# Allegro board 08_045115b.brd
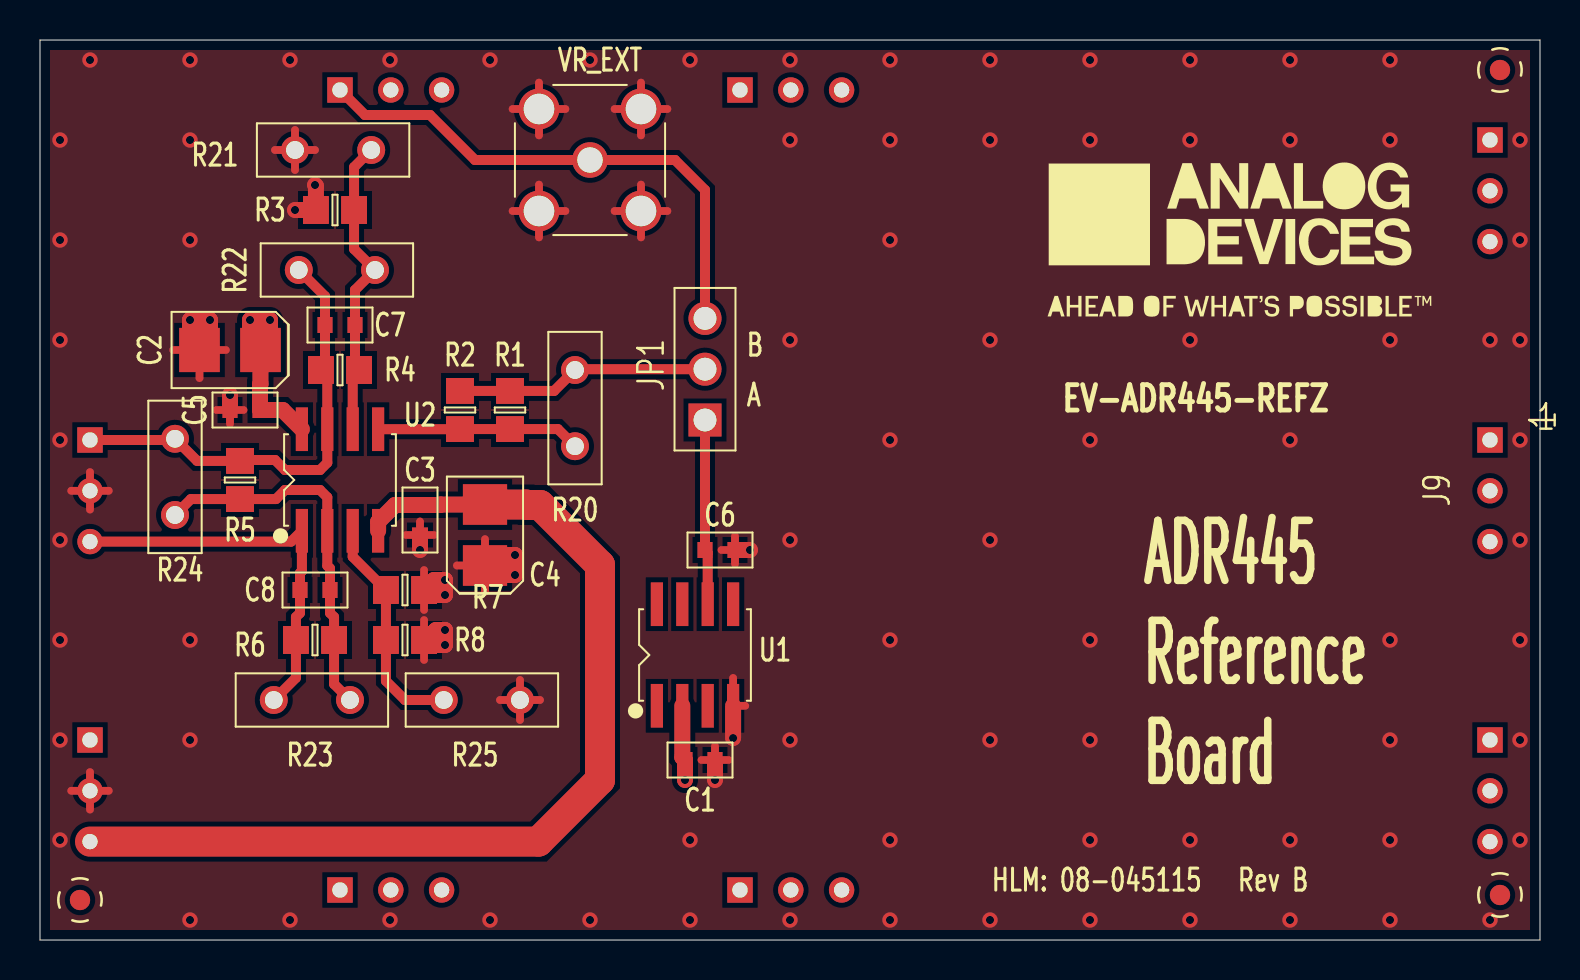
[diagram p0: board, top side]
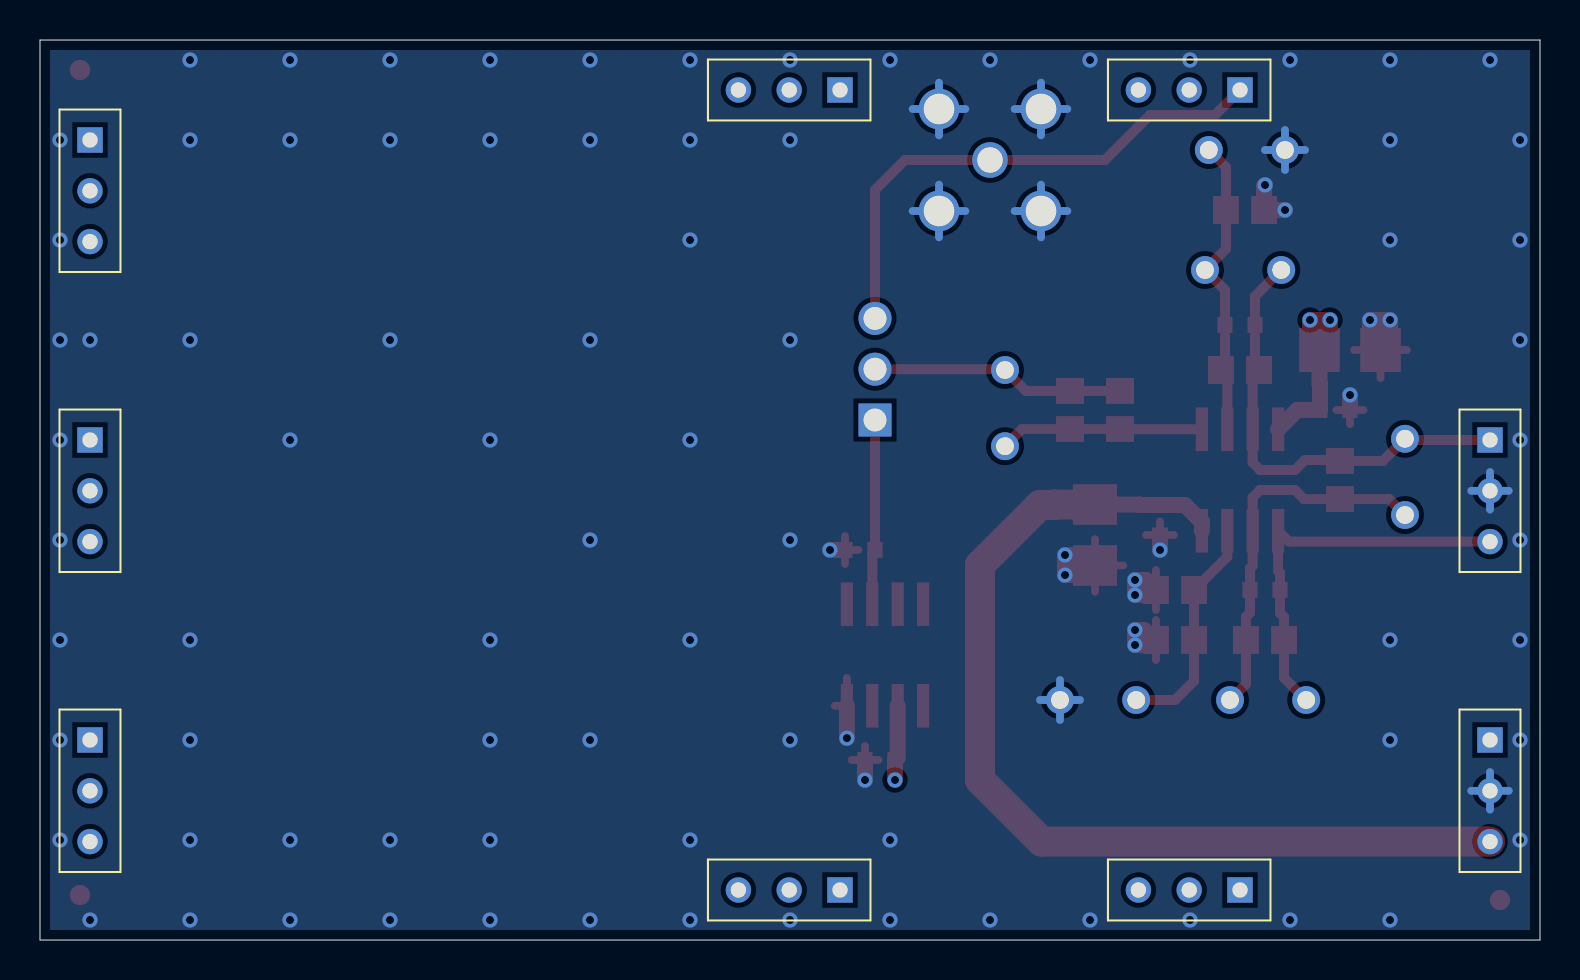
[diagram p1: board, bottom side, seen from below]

Outline 75 x 45 mm; copper layers: TOP, LAYER2, LAYER3, BOTTOM. Coordinates in mm from the lower left corner of the outline.
Outline path: 0,45 0,0 75,0 75,45 0,45

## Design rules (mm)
constraint set DEFAULT: min track width 0.19

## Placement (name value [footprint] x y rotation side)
C1  0.1UF  [C0603]  33 9 180 top
C2  10uF  [C3528]  9.5 29.5 180 top
C3  0.1UF  [C0603]  19 21 270 top
C4  10uF  [C3528]  22.25 20.25 90 top
C5  0.1UF  [C0603]  10.25 26.5 0 top
C6  0.1UF  [C0603]  34 19.5 180 top
C7  0.1UF  [C0603]  15 30.75 180 top
C8  0.1UF  [C0603]  13.75 17.5 180 top
J1  350-10-103-00-006000  [CNTHMHDR1X3L300W100H284]  2.5 10 270 bottom
J2  350-10-103-00-006000  [CNTHMHDR1X3L300W100H284]  35 42.5 0 bottom
J3  350-10-103-00-006000  [CNTHMHDR1X3L300W100H284]  15 42.5 0 bottom
J4  310-13-103-41-001000  [CNTHFHDR1X3L300W100H165]  2.5 25 270 bottom
J5  310-13-103-41-001000  [CNTHFHDR1X3L300W100H165]  72.5 40 270 bottom
J6  310-13-103-41-001000  [CNTHFHDR1X3L300W100H165]  15 2.5 0 bottom
J7  350-10-103-00-006000  [CNTHMHDR1X3L300W100H284]  35 2.5 0 bottom
J8  350-10-103-00-006000  [CNTHMHDR1X3L300W100H284]  72.5 10 270 bottom
J9  350-10-103-00-006000  [CNTHMHDR1X3L300W100H284]  72.5 25 270 bottom
JP1  M20-9990345  [CNHDR1X3H340]  33.25 26 90 top
NOREF  -  [unnamed]  73 2.25 0 top
NOREF#2  -  [#2]  0 45 0 top
NOREF#3  -  [unnamed]  73 43.5 0 top
NOREF#4  -  [unnamed]  2 2 0 top
NOREF#5  -  [#2]  -105 -95 0 top
NOREF#6  -  [#2]  36.75 -16.25 0 top
NOREF#7  -  [#2]  -100 -95 0 top
NOREF#8  -  [#2]  60 35 0 top
NOREF#9  -  [#2]  0 0 90 top
R1  10K  [R0805]  23.5 26.5 270 top
R2  10K  [R0805]  21 26.5 270 top
R3  10K  [R0805]  14.75 36.5 0 top
R4  10K  [R0805]  15 28.5 180 top
R5  10K  [R0805]  10 23 90 top
R6  10K  [R0805]  13.75 15 180 top
R7  10K  [R0805]  18.25 17.5 180 top
R8  10K  [R0805]  18.25 15 180 top
R20  10K  [RRADTH150L300H336W105LD25]  26.75 28.5 270 top
R21  10K  [RRADTH150L300H336W105LD25]  12.75 39.5 0 top
R22  10K  [RRADTH150L300H336W105LD25]  16.75 33.5 180 top
R23  10K  [RRADTH150L300H336W105LD25]  15.5 12 180 top
R24  10K  [RRADTH150L300H336W105LD25]  6.75 21.25 90 top
R25  10K  [RRADTH150L300H336W105LD25]  24 12 180 top
U1  ADR445BRZ  [SO8]  32.75 14.25 0 top
U2  ADA4077-2BRZ  [SO8]  15 23 0 top
VR_EXT  1-1337482-0  [CNBNCSQ276H299]  27.5 39 0 top

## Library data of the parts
C1 C3 C5-C8 = CAP: User Part Number: UPN; Tolerance: 10; alternate symbols: (); part number: CAP_SM-0.1UF,25V,10,E007204,C0603; tolerance: 10
C2 C4 = CAPP: User Part Number: UPN; Tolerance: N/A; alternate symbols: (); part number: CAPP_SM-10UF,N/A,N/A,E000695,C3528; tolerance: N/A
J1-J3 J7-J9 = CN3P: User Part Number: UPN; Tolerance: N/A; alternate symbols: (); part number: CN3P_TH-350-10-103-00-006000,E027762,CNTHMHDR1X3L300W100H284; tolerance: N/A
J4-J6 = CN3P: User Part Number: UPN; Tolerance: N/A; alternate symbols: (); part number: CN3P_TH-310-13-103-41-001000,E027752,CNTHFHDR1X3L300W100H165; tolerance: N/A
JP1 = CN3P_JMPRSHRT: Tolerance: N/A; User Part Number: UPN; alternate symbols: (); part number: CN3P_JMPRSHRT_TH-M20-9990345,E029424,CNHDR1X3H340; tolerance: N/A
R1-R8 = RES: User Part Number: UPN; Tolerance: 0.1; alternate symbols: (R0805L); part number: RES_SM-10K,E003806,1/8W,0.1,R0805; tolerance: 0.1
R20-R25 = RES: Tolerance: 0.005; User Part Number: UPN; alternate symbols: (); part number: RES_TH-10K,E018578,6/10W,0.005,RRADTH150L300H336W105LD25; tolerance: 0.005
U1 = ADR441: User Part Number: UPN; Tolerance: N/A; alternate symbols: (); part number: ADR441_SM-ADR445BRZ,E012504,SO8; tolerance: N/A
U2 = ADA4077_2: User Part Number: UPN; Tolerance: N/A; alternate symbols: (); part number: ADA4077_2_SM-ADA4077-2BRZ,E018506,SO8; tolerance: N/A
VR_EXT = CNBNC5P: Tolerance: N/A; User Part Number: UPN; alternate symbols: (); part number: CNBNC5P_TH-1-1337482-0,E013941,CNBNCSQ276H299; tolerance: N/A

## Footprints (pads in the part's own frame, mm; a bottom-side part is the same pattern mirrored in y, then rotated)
C0603
  rect 0.75x0.8 smd: 1(-0.75,0) 2(0.75,0)
C3528
  rect 2.032x2.21 smd: N(1.524,0) P(-1.524,0)
CNBNCSQ276H299
  round 1.778 hole 1.27: 1(0,0)
  round 2.032 hole 1.524: 2(-2.55,2.55) 3(2.55,2.55) 4(2.55,-2.55) 5(-2.55,-2.55)
CNHDR1X3H340
  rect 1.651x1.651 hole 1.143: 1(0,0)
  round 1.651 hole 1.143: 2(2.54,0) 3(5.08,0)
CNTHFHDR1X3L300W100H165
  rect 1.27x1.27 hole 0.762: 1(0,0)
  round 1.27 hole 0.762: 2(2.54,0) 3(5.08,0)
CNTHMHDR1X3L300W100H284
  rect 1.27x1.27 hole 0.762: 1(0,0)
  round 1.27 hole 0.762: 2(2.54,0) 3(5.08,0)
R0805
  rect 1.295x1.397 smd: 1(-0.953,0) 2(0.953,0)
RRADTH150L300H336W105LD25
  round 1.397 hole 0.889: 1(0,0) 2(3.81,0)
SO8
  rect 0.61x2.184 smd: 1(-1.905,-2.54) 2(-0.635,-2.54) 3(0.635,-2.54) 4(1.905,-2.54) 5(1.905,2.54) 6(0.635,2.54) 7(-0.635,2.54) 8(-1.905,2.54)
unnamed
  round 1.016 smd: (0,0)

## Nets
AGND: C1.1(N1) C2.N(N2) C3.2(N2) C4.P(N1) C5.1(N1) C6.1(N1) J1.2(N2) J4.2(N2) R3.1(N1) R7.1(N1) R8.1(N1) R21.1(N1) R25.1(N1) U1.4(GND) VR_EXT.2(SH1) VR_EXT.3(SH2) VR_EXT.4(SH3) VR_EXT.5(SH4)
VDD: C1.2(N2) C2.P(N1) C5.2(N2) J1.1(N1) U1.2(VIN) U2.8(V+)
VSS: C3.1(N1) C4.N(N2) J1.3(N3) U2.4(V-)
UNNAMED_2_ADA40772_I74_: C7.1(N1) R3.2(N2) R4.1(N1) R21.2(N2) R22.1(N1) U2.6(-IN)
UNNAMED_2_ADA40772_I74__1: R1.2(N2) R2.2(N2) R20.2(N2) U2.5(+IN)
UNNAMED_2_ADA40772_I75_: C8.1(N1) R5.1(N1) R6.1(N1) R23.1(N1) R24.1(N1) U2.2(-IN)
UNNAMED_2_ADA40772_I75__1: R7.2(N2) R8.2(N2) R25.2(N2) U2.3(+IN)
UNNAMED_2_ADR441_I1_VOUT: C6.2(N2) JP1.1(S1) U1.6(VOUT)
UNNAMED_2_CN3P_I64_N1: J3.1(N1) JP1.3(S3) VR_EXT.1(CNTR)
UNNAMED_2_CN3PJMPRSHRT_I77_S2: JP1.2(S2) R1.1(N1) R2.1(N1) R20.1(N1)
VREFN: C8.2(N2) J4.3(N3) R6.2(N2) R23.2(N2) U2.1(OUT)
VREFP: C7.2(N2) J4.1(N1) R4.2(N2) R5.2(N2) R22.2(N2) R24.2(N2) U2.7(OUT)

Pads without a net: J2 1 2 3; J3 2 3; J5 1 2 3; J6 1 2 3; J7 1 2 3; J8 1 2 3; J9 1 2 3; U1 1 3 5 7 8

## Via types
v1: diameter 0.762, hole 0.406, TOP to BOTTOM, 97 vias

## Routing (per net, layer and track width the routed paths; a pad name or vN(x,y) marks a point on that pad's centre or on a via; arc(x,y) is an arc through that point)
AGND: length 156.1
  TOP w0.39: C1.1 33.75,9.7 ; C1.1 33.07,9 ; C1.1 34.43,9 ; 19.2,14 R8.1 19.2,16 ; C4.P 23.66,18.73 ; C4.P 22.25,20.04 ; C4.P 22.25,17.41 ; C4.P 20.84,18.73 ; 11.75,39.5 R21.1 ; R21.1 13.75,39.5 ; R21.1 12.75,40.5 ; R21.1 12.75,38.5 ; C3.2 19,20.93 ; C3.2 19.7,20.25 ; C3.2 18.3,20.25 ; C6.1 34.75,20.2 ; C6.1 34.75,18.8 ; C6.1 34.07,19.5 ; 28.73,36.45 VR_EXT.4 ; VR_EXT.4 30.05,37.77 ; VR_EXT.4 30.05,35.13 ; VR_EXT.4 31.37,36.45 ; J1.2 3.44,7.46 ; J1.2 2.5,8.4 ; J1.2 1.56,7.46 ; J1.2 2.5,6.52 ; C5.1 10.18,26.5 ; C5.1 9.5,25.8 ; C5.1 8.82,26.5 ; 24.95,35.13 VR_EXT.5 ; VR_EXT.5 24.95,37.77 ; VR_EXT.5 26.27,36.45 ; VR_EXT.5 23.63,36.45 ; 23,12 R25.1 ; R25.1 25,12 ; R25.1 24,11 ; R25.1 24,13 ; VR_EXT.3 31.37,41.55 ; VR_EXT.3 30.05,42.87 ; VR_EXT.3 28.73,41.55 ; VR_EXT.3 30.05,40.23 ; VR_EXT.2 24.95,42.87 ; VR_EXT.2 23.63,41.55 ; VR_EXT.2 24.95,40.23 ; VR_EXT.2 26.27,41.55 ; 19.2,16.5 R7.1 ; R7.1 19.2,18.5 ; R7.1 20.15,17.5 ; 2.5,21.52 J4.2 ; J4.2 3.44,22.46 ; J4.2 1.56,22.46 ; J4.2 2.5,23.4 ; 35.26,11.71 U1.4 34.66,13.1 ; 6.66,29.5 C2.N ; C2.N 9.29,29.5 ; C2.N 7.98,28.09
  TOP w0.8: 19.75,15 R8.1 ; 19.75,15 19.75,15.45 19.8,15.5 v1(20.25,15.5) v1(20.25,14.75) 19.8,14.75 19.75,14.8 19.75,15 ; 7.98,30.48 C2.N ; 7.98,30.48 8.45,30.48 8.5,30.53 v1(8.5,31) v1(7.5,31) 7.5,30.53 7.55,30.48 7.98,30.48 ; C6.1 v1(35.5,19.5) ; C3.2 v1(19,19.5) ; v1(13.75,37.75) 13.8,37.7 R3.1 v1(12.75,36.5) ; U1.4 v1(34.66,10.1) ; C5.1 v1(9.5,27.25) ; C1.1 v1(33.75,8) ; v1(23.75,19.25) 22.77,19.25 C4.P 22.73,18.25 v1(23.75,18.25) v1(23.75,19.25) ; v1(20.25,17.25) v1(20.25,18) 19.7,18 R7.1 19.45,17.25 v1(20.25,17.25)
  LAYER2 w0.39: R21.1 12.75,40.5 ; R21.1 13.75,39.5 ; R21.1 11.75,39.5 ; R21.1 12.75,38.5 ; VR_EXT.2 26.27,41.55 ; VR_EXT.2 23.63,41.55 ; VR_EXT.2 24.95,42.87 ; VR_EXT.2 24.95,40.23 ; J1.2 2.5,8.4 ; J1.2 1.56,7.46 ; J1.2 2.5,6.52 ; J1.2 3.44,7.46 ; J4.2 2.5,23.4 ; J4.2 1.56,22.46 ; J4.2 3.44,22.46 ; J4.2 2.5,21.52 ; VR_EXT.4 31.37,36.45 ; VR_EXT.4 30.05,35.13 ; VR_EXT.4 28.73,36.45 ; VR_EXT.4 30.05,37.77 ; R25.1 25,12 ; R25.1 24,11 ; R25.1 24,13 ; R25.1 23,12 ; 23.63,36.45 VR_EXT.5 ; VR_EXT.5 24.95,37.77 ; VR_EXT.5 24.95,35.13 ; VR_EXT.5 26.27,36.45 ; 28.73,41.55 VR_EXT.3 ; VR_EXT.3 31.37,41.55 ; VR_EXT.3 30.05,40.23 ; VR_EXT.3 30.05,42.87
  BOTTOM w0.39: R21.1 12.75,40.5 ; R21.1 13.75,39.5 ; R21.1 11.75,39.5 ; R21.1 12.75,38.5 ; R25.1 25,12 ; R25.1 24,11 ; R25.1 24,13 ; R25.1 23,12 ; 23.63,41.55 VR_EXT.2 ; VR_EXT.2 24.95,42.87 ; VR_EXT.2 26.27,41.55 ; VR_EXT.2 24.95,40.23 ; 23.63,36.45 VR_EXT.5 ; VR_EXT.5 26.27,36.45 ; VR_EXT.5 24.95,35.13 ; VR_EXT.5 24.95,37.77 ; VR_EXT.3 31.37,41.55 ; VR_EXT.3 30.05,42.87 ; VR_EXT.3 28.73,41.55 ; VR_EXT.3 30.05,40.23 ; J4.2 3.44,22.46 ; J4.2 1.56,22.46 ; J4.2 2.5,21.52 ; J4.2 2.5,23.4 ; VR_EXT.4 31.37,36.45 ; VR_EXT.4 30.05,37.77 ; VR_EXT.4 28.73,36.45 ; VR_EXT.4 30.05,35.13 ; J1.2 3.44,7.46 ; J1.2 2.5,6.52 ; J1.2 2.5,8.4 ; J1.2 1.56,7.46
  vias: v1(1,40) v1(1,35) v1(1,30) v1(1,25) v1(1,20) v1(1,15) v1(1,10) v1(1,5) v1(2.5,44) v1(7.5,44) v1(7.5,40) v1(7.5,35) v1(7.5,15) v1(7.5,10) v1(7.5,1) v1(12.5,44) v1(12.5,1) v1(17.5,44) v1(17.5,1) v1(22.5,44) v1(22.5,1) v1(27.5,44) v1(27.5,1) v1(32.5,44) v1(32.5,5) v1(32.5,1) v1(37.5,44) v1(37.5,40) v1(37.5,30) v1(37.5,20) v1(37.5,10) v1(37.5,1) v1(42.5,44) v1(42.5,40) v1(42.5,35) v1(42.5,25) v1(42.5,15) v1(42.5,5) v1(42.5,1) v1(47.5,44) v1(47.5,40) v1(47.5,30) v1(47.5,20) v1(47.5,10) v1(47.5,1) v1(52.5,44) v1(52.5,40) v1(52.5,25) v1(52.5,15) v1(52.5,10) v1(52.5,5) v1(52.5,1) v1(57.5,44) v1(57.5,40) v1(57.5,30) v1(57.5,5) v1(57.5,1) v1(62.5,44) v1(62.5,40) v1(62.5,25) v1(62.5,5) v1(62.5,1) v1(67.5,44) v1(67.5,40) v1(67.5,30) v1(67.5,15) v1(67.5,10) v1(67.5,5) v1(67.5,1) v1(72.5,30) v1(72.5,1) v1(74,40) v1(74,35) v1(74,30) v1(74,25) v1(74,20) v1(74,15) v1(74,10) v1(74,5)
VDD: length 16.1
  TOP w0.8: U2.8 12.13,26.5 C5.2 11,27.77 11.02,27.8 C2.P 11.19,29.66 11.19,29.94 ; U1.2 32.12,9.13 C1.2 v1(32.25,8) ; 11.19,29.94 10.5,30.62 v1(10.5,31) v1(11.5,31) 11.5,30.25 11.19,29.94
  LAYER3 w0.39: 2.5,9.06 J1.1 ; J1.1 3.44,10 ; J1.1 2.5,10.94
VSS: length 50.7
  TOP w0.8: U2.4 16.91,20.91 17.75,21.75 C3.1 20,21.75 20.02,21.77 C4.N
  TOP w1.5: C4.N 24.3,21.77 24.33,21.75 25,21.75 28,18.75 28,8 24.92,4.92 J1.3
UNNAMED_2_ADA40772_I74_: length 15.4
  TOP w0.5: R21.2 15.7,38.64 R3.2 15.7,34.55 R22.1 15.75,32.5 C7.1 15.75,28.7 R4.1 15.63,28.18 U2.6
UNNAMED_2_ADA40772_I74__1: length 10.2
  TOP w0.5: U2.5 20.99,25.54 R2.2 R1.2 25.89,25.55 R20.2
UNNAMED_2_ADA40772_I75_: length 18.9
  TOP w0.5: R23.1 14.7,12.8 R6.1 14.7,16.15 14.5,16.35 C8.1 14.5,18.58 14.37,18.71 U2.2 14.37,22.14 14,22.5 12.25,22.5 11.8,22.05 R5.1 7.55,22.05 R24.1
UNNAMED_2_ADA40772_I75__1: length 11.5
  TOP w0.5: R25.2 18.25,12 17.3,12.95 R8.2 R7.2 15.63,19.16 U2.3
UNNAMED_2_ADR441_I1_VOUT: length 9.3
  TOP w0.5: JP1.1 C6.2 33.38,19.36 U1.6
UNNAMED_2_CN3P_I64_N1: length 26.7
  TOP w0.5: J3.1 16.25,41.25 19.5,41.25 21.75,39 VR_EXT.1 31.75,39 33.25,37.5 JP1.3
UNNAMED_2_CN3PJMPRSHRT_I77_S2: length 12.7
  TOP w0.5: JP1.2 26.79,28.54 R20.1 25.7,27.45 R1.1 R2.1
VREFN: length 19.9
  TOP w0.5: J4.3 12.55,19.92 U2.1 13.1,18.45 13,18.35 C8.2 13,16.35 12.8,16.15 R6.2 12.8,13.11 R23.2
VREFP: length 23.1
  TOP w0.5: J4.1 6.69,25 R24.2 7.86,23.95 R5.2 10.05,24 11.75,24 12.25,23.5 14,23.5 14.37,23.86 U2.7 14.37,28.18 R4.2 14.25,28.7 C7.2 14.25,32.19 R22.2

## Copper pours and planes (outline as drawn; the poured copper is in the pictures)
AGND on TOP, BOTTOM, LAYER2: 0.5,44.5 0.5,0.5 74.5,0.5 74.5,44.5
VDD on LAYER3: 0.5,44.5 0.5,0.5 74.5,0.5 74.5,44.5

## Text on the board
Ref Des/Assembly Top: B | A | ADD JUMPER BUSBAR IN LOCATION 'A' OF JP1
Ref Des/Silkscreen Top: B | A | HLM: 08-045115   Rev B | EV-ADR445-REFZ | ADR445 | Reference | Board
LAYER2: L2 Internal GND | 08-      -07
LAYER3: L3 Internal PWR | 08-      -08
XSECTION_CHART: Primary Side Silkscreen | Primary Side Soldermask | 0.035 (1oz) Copper Plating | Primary side 0.017 (0.5oz) Copper Foil | FR4 Prepreg | 0.035 (1oz) Copper | Secondary Side 0.017 (0.5oz) Copper Foil | FR4 CORE | Secondary Side Soldermask | Secondary side Silkscreen | 1.6mm +/-10% | 4 LAYER STACKUP
User.20: ADR445 REFERENCE BOARD
User.23: 10. Manufacturer UL and Date codes on the bottom side silkscreen as indicated. | 1. Material: 4 Layer FR4 glass epoxy laminate 1.6mm +/- 10%. material to be RoHS compliant. | 2. Plated thru holes and conductive pattern electroplated with 0.255mm min. thick copper. | 3. Processing tolerence: | 4. Warp and twist within 0.1875mm per 25mm (0.75%) | 5. Dimensions are for the finished part. | 6. SOLDERMASK: liquid Photo Imeagable soldermask over bare copper (SMOBC), | 7. SCREENING: Screen component outlines and nomenclature using indelible white ink on both sides. | 8. Electrically test 100%. | 9. Break all sharp edges 0.35mm Radius max. | Board to be fabricated per IPC-6012A, CLASS 2. | Terminal areas and plated thru holes to be ENIG plated. | colour GREEN both sides using the pattern provided. No mask is permitted on the terminal areas. | Soldermask to etch registration within 0.125mm total. | A. Conductive pattern front to back registration within 0.125mm total. | B. Minimum annual ring surrounding holes 0.05mm. | C. Finished conductive pattern to be within 0.05mm of true size. | D. Minimumfeature size 0.2mm | E. Minimum air gap 0.12mm | Nomenclature shall be legible. Screen to etch registration within 0.15mm total. | FABRICATION NOTES: | 1 | FABRICATION | 09-045115-01 | B
